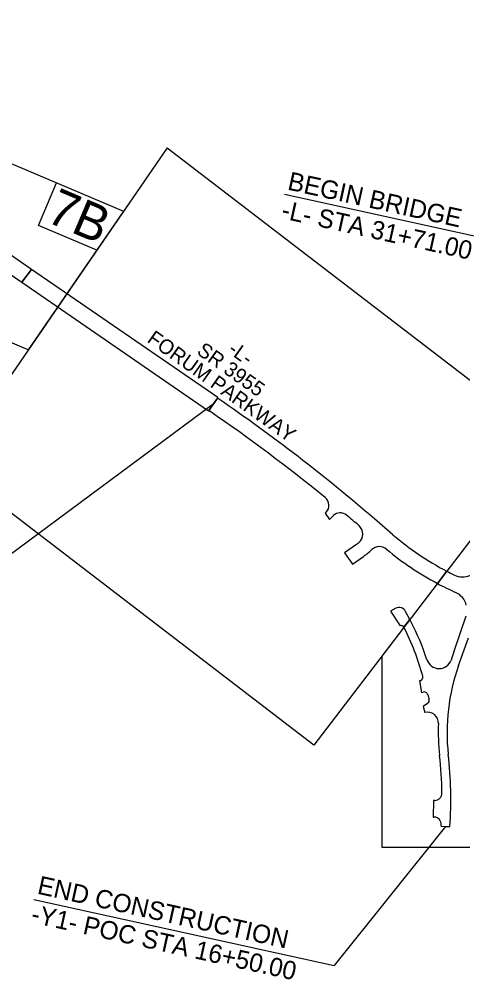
# Model space of a CAD drawing. Extents: x 1609449 to 1623942, y 894240 to 902860.
# Drawn here: x 1618272 to 1619483, y 897036 to 899656 of the extents above; entities that cross this region are included whole.
import ezdxf

# ---------------------------------------------------------------- set-up
doc = ezdxf.new("R2010")
doc.units = 0
for name, color, linetype in [('Old_Level_1', 7, 'Continuous'), ('Prop Horizontal Alignment Station Label', 7, 'Continuous'), ('Prop Roadway Bridge', 7, 'Continuous'), ('Prop Shade Light', 7, 'Continuous')]:
    doc.layers.add(name, color=color, linetype=linetype)

msp = doc.modelspace()

# ---------------------------------------------------------------- linework, layer by layer
at = {"layer": 'Old_Level_1'}
for p, q in [((1618675.4, 899305), (1618079.6, 898438.7)), ((1618324.1, 899093.3), (1618373.4, 899209.8)), ((1618483.4, 899025.8), (1618324.1, 899093.3))]:
    msp.add_line(p, q, dxfattribs=at)
for points in [[(1618296.3, 898753.8), (1617312.4, 899170.5), (1617320.4, 899655.8), (1618556.6, 899132.2)], [(1619261.8, 897919), (1619261.8, 897398.3), (1620661.8, 897398.3), (1620661.8, 898448.3), (1619667.1, 898448.3)]]:
    msp.add_lwpolyline(points, close=True, dxfattribs=at)
msp.add_lwpolyline([(1618675.4, 899305), (1619714, 898509.6), (1619075.6, 897675.9), (1618079.6, 898438.7)], dxfattribs=at)
at = {"layer": 'Prop Horizontal Alignment Station Label'}
for p, q in [((1618801.3, 898605.7), (1617939.7, 897968.5)), ((1619435.6, 897454.6), (1619131.9, 897074.8)), ((1618312, 897255.4), (1619131.9, 897074.8))]:
    msp.add_line(p, q, dxfattribs=at)
at = {"layer": 'Prop Roadway Bridge'}
msp.add_line((1618995.9, 899179), (1619599.3, 899046.1), dxfattribs=at)
at = {"layer": 'Prop Shade Light'}
for p, q in [((1618305.8, 898973.3), (1618072.3, 899133.9)), ((1618047.3, 899097.6), (1618279, 898938.3)), ((1618279, 898938.3), (1618305.8, 898973.3)), ((1618305.8, 898973.3), (1618279, 898938.3)), ((1618813.8, 898623.9), (1618305.8, 898973.3)), ((1618279, 898938.3), (1618788.9, 898587.6)), ((1618789.6, 898588.6), (1618813.1, 898622.8)), ((1618813.1, 898622.8), (1618789.6, 898588.6)), ((1618813.8, 898623.9), (1618813.1, 898622.8)), ((1618813.1, 898622.8), (1618813.8, 898623.9)), ((1618815.8, 898621), (1618813.1, 898622.8)), ((1618788.9, 898587.6), (1618789.6, 898588.6)), ((1618788.9, 898587.6), (1618789.6, 898588.6)), ((1618789.6, 898588.6), (1618792.3, 898586.8)), ((1619109.6, 898311.2), (1619107.2, 898308.8)), ((1619107.2, 898308.8), (1619119, 898291.9)), ((1619119, 898291.9), (1619129.3, 898302)), ((1619291.9, 898250), (1619241.3, 898293.4)), ((1619189.7, 898221.8), (1619160, 898200.7)), ((1619160, 898200.7), (1619182, 898169.7)), ((1619182, 898169.7), (1619211.7, 898190.8)), ((1619413.4, 898117), (1619439, 898150.4)), ((1619439, 898150.4), (1619413.4, 898117)), ((1619299.7, 898049.5), (1619285.1, 898041.9)), ((1619285.1, 898041.9), (1619311.5, 898001.3)), ((1619338.2, 898018.8), (1619326.7, 898040.9)), ((1619322, 897997.7), (1619338.2, 898018.8)), ((1619338.2, 898018.8), (1619322, 897997.7)), ((1619340.9, 898013.5), (1619338.2, 898018.8)), ((1619490.9, 898027.5), (1619459.3, 897934.4)), ((1619322, 897997.7), (1619322, 897997.7)), ((1619471.4, 897893.5), (1619498.5, 897968.9)), ((1619459.3, 897934.4), (1619451.1, 897908.1)), ((1619366.2, 897851.9), (1619364.9, 897851.5)), ((1619364.9, 897851.5), (1619370.2, 897819.8)), ((1619373.2, 897864.4), (1619373.3, 897864.1)), ((1619370.2, 897819.8), (1619374.5, 897820.9)), ((1619386.8, 897813.8), (1619388.8, 897806.2)), ((1619386.7, 897789.8), (1619374.7, 897781.6)), ((1619374.7, 897781.6), (1619379.4, 897765.5)), ((1619379.4, 897765.5), (1619379.4, 897765.5)), ((1619403, 897525.6), (1619402, 897480)), ((1619405.9, 897525.6), (1619403, 897525.6)), ((1619402, 897480), (1619404.8, 897479.9))]:
    msp.add_line(p, q, dxfattribs=at)
for points in [[(1619322, 897997.7), (1619322, 897997.7)], [(1619423.7, 897455.4), (1619435.6, 897454.6), (1619447.6, 897453.8)]]:
    msp.add_lwpolyline(points, dxfattribs=at)
for centre, radius, start, end in [((1615970.5, 894484.3), 5020.7, 49.3484, 55.4794), ((1615970.5, 894484.3), 4979.2, 50.9512, 55.4794), ((1619090.4, 898330.2), 27, 315.2913, 50.9512), ((1619148.1, 898282.6), 27, 50.0851, 134.2061), ((1615970.5, 894484.3), 4979.2, 49.5753, 50.0851), ((1619179.9, 898251.9), 30, 308.8694, 49.5753), ((1619799.5, 898841.2), 779.2, 229.3484, 242.4405), ((1619085.1, 898369.5), 181, 305.3092, 308.8694), ((1619255.1, 898187.5), 30, 50.2116, 133.0475), ((1619085.1, 898369.5), 219, 305.3092, 313.0475), ((1619799.5, 898841.2), 820.7, 230.2116, 241.9359), ((1619482.3, 898186.8), 52, 244.1387, 340.2164), ((1619799.5, 898841.2), 779.2, 242.4405, 244.1387), ((1619799.5, 898841.2), 820.7, 241.9359, 245.8136), ((1619441.9, 898045.1), 52, 14.2258, 65.8136), ((1619308.9, 898031.7), 20, 27.3974, 117.3974), ((1618709.7, 897686.3), 711, 18.2485, 27.3974), ((1619314.9, 897994.1), 8, 26.9569, 115.0072), ((1618709.7, 897686.3), 687, 15.0263, 26.9561), ((1619418.2, 897919.9), 35, 198.2485, 340.2164), ((1619977.6, 897711.4), 538, 160.2164, 186.4763), ((1619363.6, 897861.5), 10, 285.0263, 15.0263), ((1619377.1, 897811.3), 10, 15.0263, 105.0263), ((1619381, 897798), 10, 304.4312, 22.1467), ((1619424.6, 897815.8), 37, 195.0263, 202.1467), ((1619386.1, 897736.2), 30, 357.5954, 103.0108), ((1619977.6, 897711.4), 562, 177.5954, 186.4763), ((1618353, 897527), 1073, 1.0137, 6.4763), ((1618353, 897527), 1097, 356.1767, 6.4763), ((1619405.9, 897545.6), 20, 269.9254, 1.0137), ((1619403.9, 897459.9), 20, 356.3496, 87.4379), ((1618353, 897527), 1073, 356.1767, 356.3496)]:
    msp.add_arc(centre, radius, start, end, dxfattribs=at)

# ---------------------------------------------------------------- texts
at = {"layer": 'Old_Level_1'}
msp.add_text('7B', height=100, rotation=337.0441, dxfattribs=at).set_placement((1618341.2, 899105.4))
at = {"layer": 'Prop Horizontal Alignment Station Label'}
for s, height, rotation, p in [('FORUM PARKWAY', 40, 324.602, (1618618.4, 898777.3)), ('SR 3955', 40, 324.602, (1618753.9, 898744.8)), ('-L-', 40, 324.602, (1618839.2, 898748)), ('END CONSTRUCTION', 50, 347.5755, (1618318.8, 897271.4)), ('-Y1- POC STA 16+50.00', 50, 347.5755, (1618301.6, 897193.3))]:
    msp.add_text(s, height=height, rotation=rotation, dxfattribs=at).set_placement(p)
at = {"layer": 'Prop Roadway Bridge'}
for s, p in [('BEGIN BRIDGE', (1619001.9, 899191.6)), ('-L- STA 31+71.00', (1618984.7, 899113.5))]:
    msp.add_text(s, height=50, rotation=347.5755, dxfattribs=at).set_placement(p)

doc.saveas('drawing.dxf')
